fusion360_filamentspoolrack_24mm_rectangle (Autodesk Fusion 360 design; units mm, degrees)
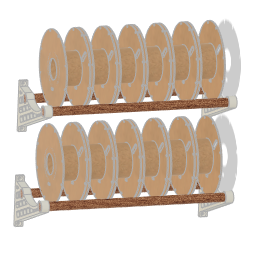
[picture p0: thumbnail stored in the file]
sketch "Skizze1" plane through (0, 0, 0) normal (0, 1, 0) x axis (1, 0, 0)
  circle C1 centre (0, 0) radius 27
  circle C2 centre (0, 0) radius 44
  circle C3 centre (0, 0) radius 41
  circle C4 centre (0, 0) radius 99.5
  point P1 (0, 0)
  point P2 (0, 0)
  coincident P1 P2
  concentric C1 C2
  concentric C2 C3
  concentric C3 C4
  dimension "d1" diameter C1 = 54
  dimension "d2" diameter C2 = 88
  dimension "d3" diameter C3 = 82
  dimension "d4" diameter C4 = 199
extrude "Extrusion1" new body sketch "Skizze1" against normal blind 3 bodies "cardboard spool 1"
extrude "Extrusion2" add sketch "Skizze1" profile of C2 C3 along normal blind 58
sketch "Skizze2" plane through (0, 58, 0) normal (0, 1, 0) x axis (-1, 0, 0)
  circle C1 centre (0, 0) radius 41
  circle C2 centre (0, 0) radius 44
  circle C3 centre (0, 0) radius 27
  circle C4 centre (0, 0) radius 99.5
  concentric C1 C3
  concentric C3 C4
  dimension "d9" diameter C3 = 54
  dimension "d10" diameter C4 = 199
extrude "Extrusion3" add sketch "Skizze2" along normal blind 3
sketch "Skizze3" plane through (0, -3, 0) normal (0, -1, 0) x axis (1, 0, 0)
  line L1 (-46.2426, 27.7574) -> (-64.2426, 45.7574)
  line L2 (-55.7574, 54.2426) -> (-37.7574, 36.2426)
  line L3 (-42, 32) -> (-60, 50)
  circle C1 centre (0, 0) radius 27
  circle C2 centre (0, 0) radius 99.5
  arc A1 centre (-42, 32) radius 6 clockwise from (-37.7574, 36.2426) to (-46.2426, 27.7574)
  arc A2 centre (-60, 50) radius 6 clockwise from (-64.2426, 45.7574) to (-55.7574, 54.2426)
  tangent L1 A1
  tangent A1 L2
  parallel L1 L2
  tangent L2 A2
  tangent L1 A2
  dimension "d13" diameter A1 = 12
extrude "Extrusion4" cut sketch "Skizze3" profile of L1 A1 L2 A2 against normal blind 3
sketch "Skizze4" plane through (0, -3, 0) normal (0, -1, 0) x axis (1, 0, 0)
  line L1 (-64.2426, 45.7574) -> (-46.2426, 27.7574)
  line L2 (-37.7574, 36.2426) -> (-55.7574, 54.2426)
  line L3 (4, -53) -> (-4, -53)
  line L4 (-4, -47) -> (4, -47)
  line L5 (4, -50) -> (-4, -50)
  arc A1 centre (-60, 50) radius 6 clockwise from (-64.2426, 45.7574) to (-55.7574, 54.2426)
  arc A2 centre (-42, 32) radius 6 clockwise from (-37.7574, 36.2426) to (-46.2426, 27.7574)
  circle C1 centre (0, 0) radius 27
  circle C2 centre (0, 0) radius 99.5
  circle C3 centre (-30, 90) radius 3
  circle C4 centre (30, 90) radius 3
  circle C5 centre (-90, -30) radius 3
  circle C6 centre (-90, 30) radius 3
  circle C7 centre (30, -90) radius 3
  circle C8 centre (-30, -90) radius 3
  circle C9 centre (90, -30) radius 3
  circle C10 centre (90, 30) radius 3
  arc A3 centre (4, -50) radius 3 clockwise from (4, -47) to (4, -53)
  arc A4 centre (-4, -50) radius 3 clockwise from (-4, -53) to (-4, -47)
  tangent L3 A3
  tangent A3 L4
  parallel L3 L4
  tangent L4 A4
  tangent L3 A4
  horizontal L5
  dimension "d16" diameter C3 = 6
  dimension "d17" diameter C4 = 6
  dimension "d18" diameter C5 = 6
  dimension "d19" diameter C6 = 6
  dimension "d20" diameter C7 = 6
  dimension "d21" diameter C8 = 6
  dimension "d22" diameter C9 = 6
  dimension "d23" diameter C10 = 6
  dimension "d24" diameter A3 = 6
extrude "Extrusion5" cut sketch "Skizze4" profile of C3 C4 C5 C6 C7 C8 C9 C10 L3 A3 L4 A4 against normal blind 100
sketch "Skizze5" plane through (0, -3, 0) normal (0, -1, 0) x axis (1, 0, 0)
  line L1 (-4, -53) -> (4, -53)
  line L2 (4, -47) -> (-4, -47)
  line L3 (-64.2426, 45.7574) -> (-46.2426, 27.7574)
  line L4 (-37.7574, 36.2426) -> (-55.7574, 54.2426)
  line L5 (60, -79.3741) -> (-60, -79.3741)
  line L6 (114, -179.9929) -> (114, 0.0071)
  line L7 (103.9489, -179.9929) -> (114, -179.9929)
  line L8 (103.9489, -51.9929) -> (103.9489, -179.9929)
  line L9 (114, -51.9929) -> (103.9489, -51.9929)
  line L10 (114, -179.9929) -> (114, -51.9929)
  line L11 (-71.8455, -102.3262) -> (103.9489, -166.9789)
  line L12 (103.9489, -158.9789) -> (103.9489, -166.9789)
  line L13 (-57.0574, -99.7649) -> (103.9489, -158.9789)
  line L14 (-46.0337, -97.145) -> (-48.1959, -103.024)
  line L15 (-43.5032, -104.7498) -> (-48.1959, -103.024)
  line L16 (-41.4565, -99.1847) -> (-43.5032, -104.7498)
  line L17 (-24.7324, -111.6533) -> (-43.5032, -104.7498)
  line L18 (-22.3416, -105.1528) -> (-24.7324, -111.6533)
  line L19 (-20.0397, -113.3791) -> (-24.7324, -111.6533)
  line L20 (-17.3586, -106.0892) -> (-20.0397, -113.3791)
  line L21 (-1.2689, -120.2825) -> (-20.0397, -113.3791)
  line L22 (3.4526, -107.4445) -> (-1.2689, -120.2825)
  line L23 (3.4238, -122.0084) -> (-1.2689, -120.2825)
  line L24 (8.8952, -107.1313) -> (3.4238, -122.0084)
  line L25 (22.1946, -128.9118) -> (3.4238, -122.0084)
  line L26 (31.8437, -102.6753) -> (22.1946, -128.9118)
  line L27 (26.8873, -130.6377) -> (22.1946, -128.9118)
  line L28 (37.9411, -100.5819) -> (26.8873, -130.6377)
  line L29 (45.6581, -137.5411) -> (26.8873, -130.6377)
  line L30 (59.1644, -100.8167) -> (45.6581, -137.5411)
  line L31 (50.3508, -139.2669) -> (45.6581, -137.5411)
  line L32 (63.8094, -102.6724) -> (50.3508, -139.2669)
  line L33 (69.1216, -146.1704) -> (50.3508, -139.2669)
  line L34 (73.8143, -147.8962) -> (69.1216, -146.1704)
  line L35 (103.9489, -65.9929) -> (103.9489, -51.9929)
  line L36 (69.5546, -73.2336) -> (103.9489, -65.9929)
  line L37 (103.9489, -73.9929) -> (103.9489, -65.9929)
  line L38 (79.1273, -79.2184) -> (103.9489, -73.9929)
  line L39 (94.9716, -75.8828) -> (69.1216, -146.1704)
  line L40 (100.7461, -74.6672) -> (73.8143, -147.8962)
  line L41 (92.5851, -154.7996) -> (73.8143, -147.8962)
  line L42 (103.9489, -123.9008) -> (92.5851, -154.7996)
  line L43 (98.0565, -139.9226) -> (8.8952, -107.1313)
  line L44 (100.8179, -132.4143) -> (98.0565, -139.9226)
  line L45 (25.0366, -104.5439) -> (100.8179, -132.4143)
  line L46 (45.9937, -97.1639) -> (103.9489, -118.4784)
  line L47 (106.7103, -110.9701) -> (103.9489, -118.4784)
  line L48 (76.276, -99.7771) -> (106.7103, -110.9701)
  line L49 (103.9489, -85.3915) -> (84.2383, -78.1424)
  line L50 (81.4769, -85.6507) -> (84.2383, -78.1424)
  line L51 (103.9489, -93.2715) -> (81.6855, -85.0836)
  circle C1 centre (-30, 90) radius 3
  circle C2 centre (30, -90) radius 3
  circle C3 centre (-30, -90) radius 3
  circle C4 centre (-90, 30) radius 3
  circle C5 centre (90, 30) radius 3
  circle C6 centre (90, -30) radius 3
  arc A1 centre (-4, -50) radius 3 clockwise from (-4, -53) to (-4, -47)
  arc A2 centre (4, -50) radius 3 clockwise from (4, -47) to (4, -53)
  circle C7 centre (-90, -30) radius 3
  circle C8 centre (30, 90) radius 3
  arc A3 centre (-60, 50) radius 6 clockwise from (-64.2426, 45.7574) to (-55.7574, 54.2426)
  arc A4 centre (-42, 32) radius 6 clockwise from (-37.7574, 36.2426) to (-46.2426, 27.7574)
  circle C9 centre (0, 0) radius 27
  circle C10 centre (0, 0) radius 99.5
  circle C11 centre (-66.6679, -88.2481) radius 11.1
  circle C12 centre (66.9737, -88.0099) radius 11.1
  circle C13 centre (-66.6679, -88.2481) radius 15
  circle C14 centre (66.9737, -88.0099) radius 15
  circle C15 centre (0, 0) radius 101
  circle C16 centre (0, 0) radius 107.5
  point P24 (-60, -79.3741)
  point P25 (60, -79.3741)
  point P1 (0, 0)
  point P29 (0, 0)
  point P36 (103.9489, -166.9789)
  point P37 (-71.8455, -102.3262)
  point P39 (-57.0574, -99.7649)
  point P40 (-48.1959, -103.024)
  point P41 (-46.0337, -97.145)
  point P43 (-41.4565, -99.1847)
  point P45 (-22.3416, -105.1528)
  point P47 (-17.3586, -106.0892)
  point P49 (3.4526, -107.4445)
  point P51 (8.8952, -107.1313)
  point P53 (31.8437, -102.6753)
  point P55 (37.9411, -100.5819)
  point P57 (59.1644, -100.8167)
  point P59 (63.8094, -102.6724)
  point P63 (69.5546, -73.2336)
  point P65 (79.1273, -79.2184)
  point P66 (94.9716, -75.8828)
  point P67 (100.7461, -74.6672)
  point P69 (103.9489, -123.9008)
  point P70 (98.0565, -139.9226)
  point P72 (25.0366, -104.5439)
  point P73 (103.9489, -118.4784)
  point P74 (45.9937, -97.1639)
  point P76 (76.276, -99.7771)
  point P77 (84.2383, -78.1424)
  point P78 (103.9489, -85.3915)
  point P80 (81.6855, -85.0836)
  point P81 (103.9489, -93.2715)
  point P31 (114, 0.0071)
  point P32 (114, -179.9929)
  point P35 (114, -51.9929)
  point P38 (103.9489, -158.9789)
  point P42 (-43.5032, -104.7498)
  point P44 (-24.7324, -111.6533)
  point P46 (-20.0397, -113.3791)
  point P48 (-1.2689, -120.2825)
  point P50 (3.4238, -122.0084)
  point P52 (22.1946, -128.9118)
  point P54 (26.8873, -130.6377)
  point P56 (45.6581, -137.5411)
  point P58 (50.3508, -139.2669)
  point P60 (69.1216, -146.1704)
  point P61 (73.8143, -147.8962)
  point P34 (103.9489, -51.9929)
  point P62 (103.9489, -65.9929)
  point P64 (103.9489, -73.9929)
  point P68 (92.5851, -154.7996)
  point P71 (100.8179, -132.4143)
  point P75 (106.7103, -110.9701)
  point P79 (81.4769, -85.6507)
  coincident C11 P24
  coincident C10 P24
  coincident C10 P25
  horizontal L5
  coincident P25 C12
  concentric C11 C13
  concentric C12 C14
  coincident P1 P29
  concentric C9 C16
  vertical L6
  horizontal L7
  vertical L8
  horizontal L9
  vertical L10
  coincident L8 P36
  coincident C13 P37
  tangent C13 L11
  parallel L8 L12
  coincident C13 P39
  parallel L11 L13
  coincident L13 P40
  coincident C16 P41
  perpendicular L13 L14
  perpendicular L14 L15
  coincident C16 P43
  perpendicular L15 L16
  perpendicular L16 L17
  coincident C16 P45
  perpendicular L13 L18
  perpendicular L18 L19
  coincident C16 P47
  perpendicular L13 L20
  perpendicular L20 L21
  coincident C16 P49
  perpendicular L13 L22
  perpendicular L22 L23
  coincident C16 P51
  perpendicular L23 L24
  perpendicular L24 L25
  coincident C16 P53
  perpendicular L13 L26
  perpendicular L26 L27
  coincident C16 P55
  perpendicular L13 L28
  perpendicular L28 L29
  coincident C14 P57
  perpendicular L29 L30
  perpendicular L30 L31
  coincident C14 P59
  perpendicular L31 L32
  perpendicular L32 L33
  perpendicular L28 L34
  perpendicular L9 L35
  coincident C15 P63
  coincident C14 P63
  parallel L8 L37
  coincident C14 P65
  parallel L36 L38
  coincident L38 P66
  perpendicular L33 L39
  coincident L38 P67
  perpendicular L34 L40
  perpendicular L40 L41
  coincident L8 P69
  perpendicular L13 L42
  coincident L42 P70
  perpendicular L42 L43
  perpendicular L43 L44
  coincident C16 P72
  perpendicular L26 L45
  coincident L8 P73
  coincident C16 P74
  perpendicular L30 L46
  perpendicular L46 L47
  coincident C14 P76
  perpendicular L39 L48
  coincident L38 P77
  coincident L8 P78
  perpendicular L40 L49
  perpendicular L49 L50
  coincident C14 P80
  coincident L50 P80
  coincident L8 P81
  perpendicular L40 L51
  dimension "d27" diameter C11 = 22.2
  dimension "d28" diameter C12 = 22.2
  dimension "d29" diameter C13 = 30
  dimension "d30" diameter C14 = 30
  dimension "d31" diameter C15 = 202
  dimension "d32" diameter C16 = 215
  dimension "d33" distance P31 P32 = 180
  dimension "d34" distance P32 P35 = 128
  dimension "d35" distance P36 P38 = 8
  dimension "d36" distance P40 P42 = 5
  dimension "d37" distance P42 P44 = 20
  dimension "d38" distance P44 P46 = 5
  dimension "d39" distance P46 P48 = 20
  dimension "d40" distance P48 P50 = 5
  dimension "d41" distance P50 P52 = 20
  dimension "d42" distance P52 P54 = 5
  dimension "d43" distance P54 P56 = 20
  dimension "d44" distance P56 P58 = 5
  dimension "d45" distance P58 P60 = 20
  dimension "d46" distance P60 P61 = 5
  dimension "d47" distance P34 P62 = 14
  dimension "d48" distance P62 P64 = 8
  dimension "d49" distance P61 P68 = 20
  dimension "d50" distance P70 P71 = 8
  dimension "d51" distance P73 P75 = 8
  dimension "d52" distance P77 P79 = 8
extrude "Extrusion6" new body sketch "Skizze5" profile of C10 C11 L5 C12 C13 C14 C15 C16 L6 L7 L8 L9 L10 L11 L12 L13 L14 L15 L16 L17 L18 L19 L20 L21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 along normal blind 20
sketch "Skizze6" plane through (103.9489, 0, 0) normal (-1, 0, 0) x axis (0, 0, 1)
  line L1 (-65.9929, -3) -> (-51.9929, -3)
  line L2 (-65.9929, -23) -> (-65.9929, -3)
  line L3 (-51.9929, -23) -> (-65.9929, -23)
  line L4 (-51.9929, -3) -> (-51.9929, -23)
  circle C1 centre (-59, -13) radius 2.5
  dimension "d55" diameter C1 = 5
sketch "Skizze7" plane through (103.9489, 0, 0) normal (-1, 0, 0) x axis (0, 0, 1)
  line L1 (-179.9929, -3) -> (-166.9789, -3)
  line L2 (-179.9929, -23) -> (-179.9929, -3)
  line L3 (-166.9789, -23) -> (-179.9929, -23)
  line L4 (-166.9789, -3) -> (-166.9789, -23)
  circle C1 centre (-173, -13) radius 2.5
  dimension "d56" diameter C1 = 5
extrude "Extrusion7" cut sketch "Skizze6" + "Skizze7" profile of S1:C1 S2:C1 blind -15
fillet "Abrundung1" radius 2
fillet "Abrundung2" radius 1
chamfer "Fase" distance 4
sketch "Skizze8" plane through (0, -3, 0) normal (0, 1, 0) x axis (-1, 0, 0)
  line L1 (23.1301, -107.2966) -> (24.042, -109.7762)
  line L2 (42.8128, -102.8728) -> (42.1706, -101.1266)
  line L3 (26.6094, -110.9629) -> (41.6261, -105.4402)
  line L4 (-81.5517, -112.3722) -> (-78.0447, -121.9079)
  line L5 (-65.3483, -104.2821) -> (-80.365, -109.8048)
  line L6 (-59.2739, -115.0045) -> (-62.7809, -105.4688)
  line L7 (-75.4773, -123.0947) -> (-60.4607, -117.5719)
  line L8 (46.6592, -98.8457) -> (47.5055, -101.1469)
  line L9 (50.0729, -102.3336) -> (54.1541, -100.8327)
  line L10 (-81.1628, -133.7095) -> (-96.1794, -139.2322)
  line L11 (-74.5047, -146.0191) -> (-78.5954, -134.8962)
  line L12 (-90.708, -154.1093) -> (-75.6914, -148.5865)
  line L13 (-97.3662, -141.7997) -> (-93.2755, -152.9225)
  line L14 (-103.9489, -119.8738) -> (-103.9489, -123.5447)
  line L15 (-88.8118, -112.9114) -> (-102.6393, -117.9967)
  line L16 (-82.7374, -123.6338) -> (-86.2444, -114.0981)
  line L17 (-98.9408, -131.7239) -> (-83.9242, -126.2012)
  line L18 (-103.826, -124.235) -> (-101.5082, -130.5372)
  line L19 (-98.3438, -81.1991) -> (-100.0718, -76.5005)
  line L20 (-101.2586, -84.402) -> (-99.5306, -83.7665)
  line L21 (-103.9489, -77.1908) -> (-103.9489, -82.525)
  line L22 (-57.6993, -125.0802) -> (-72.7159, -130.603)
  line L23 (-51.0412, -137.3899) -> (-55.1319, -126.267)
  line L24 (-67.2445, -145.48) -> (-52.2279, -139.9573)
  line L25 (-73.9027, -133.1704) -> (-69.812, -144.2933)
  line L26 (-34.2358, -116.451) -> (-49.2524, -121.9737)
  line L27 (-27.5777, -128.7606) -> (-31.6684, -117.6377)
  line L28 (-43.781, -136.8507) -> (-28.7644, -131.328)
  line L29 (-50.4392, -124.5411) -> (-46.3485, -135.664)
  line L30 (-96.9778, -90.7077) -> (-102.6393, -92.7898)
  line L31 (-90.3864, -102.8356) -> (-94.4103, -91.8944)
  line L32 (-101.2586, -108.9651) -> (-91.5732, -105.403)
  line L33 (-103.9489, -94.6669) -> (-103.9489, -107.088)
  line L34 (-93.7241, -79.2748) -> (-93.6511, -79.4732)
  line L35 (-91.0455, -76.7094) -> (-91.435, -76.6273)
  line L36 (-91.0837, -80.66) -> (-90.7671, -80.5435)
  line L37 (-84.664, -86.179) -> (-88.5309, -87.6011)
  line L38 (-83.1263, -102.2965) -> (-79.2565, -100.8733)
  line L39 (-89.7176, -90.1686) -> (-85.6937, -101.1098)
  line L40 (-2.4433, -110.1889) -> (0.5785, -118.4055)
  line L41 (19.3493, -111.502) -> (17.9243, -107.6274)
  line L42 (3.1459, -119.5922) -> (18.1626, -114.0695)
  line L43 (-31.1531, -104.5533) -> (-30.7726, -105.5879)
  line L44 (-29.4888, -106.1813) -> (-28.0577, -105.6549)
  line L45 (-58.0882, -103.743) -> (-54.5812, -113.2786)
  line L46 (-46.777, -97.452) -> (-56.9015, -101.1756)
  line L47 (-35.8104, -106.3752) -> (-37.6272, -101.4354)
  line L48 (-52.0138, -114.4654) -> (-36.9972, -108.9426)
  line L49 (-26.9757, -115.9118) -> (-22.885, -127.0347)
  line L50 (-10.7723, -107.8217) -> (-25.7889, -113.3444)
  line L51 (-4.1142, -120.1313) -> (-8.2049, -109.0084)
  line L52 (-20.3175, -128.2215) -> (-5.3009, -122.6987)
  line L53 (-103.9489, -51.9929) -> (-103.9489, -65.9929)
  line L54 (-114, -51.9929) -> (-103.9489, -51.9929)
  line L55 (-114, -179.9929) -> (-114, -51.9929)
  line L56 (-103.9489, -179.9929) -> (-114, -179.9929)
  line L57 (-103.9489, -166.9789) -> (-103.9489, -179.9929)
  line L58 (71.8455, -102.3262) -> (-103.9489, -166.9789)
  line L59 (-103.9489, -65.9929) -> (-69.5546, -73.2336)
  arc A1 centre (25.9191, -109.0858) radius 2 clockwise from (26.6094, -110.9629) to (24.042, -109.7762)
  arc A2 centre (25.0072, -106.6062) radius 2 clockwise from (23.1301, -107.2966) to (24.5504, -104.6591)
  arc A3 centre (0, 0) radius 107.5 clockwise from (39.5576, -99.9572) to (24.5504, -104.6591)
  arc A4 centre (40.2935, -101.8169) radius 2 clockwise from (39.5576, -99.9572) to (42.1706, -101.1266)
  arc A5 centre (40.9357, -103.5631) radius 2 clockwise from (42.8128, -102.8728) to (41.6261, -105.4402)
  arc A6 centre (-76.1676, -121.2176) radius 2 clockwise from (-75.4773, -123.0947) to (-78.0447, -121.9079)
  arc A7 centre (-79.6746, -111.6819) radius 2 clockwise from (-81.5517, -112.3722) to (-80.365, -109.8048)
  arc A8 centre (-64.658, -106.1592) radius 2 clockwise from (-65.3483, -104.2821) to (-62.7809, -105.4688)
  arc A9 centre (-61.151, -115.6948) radius 2 clockwise from (-59.2739, -115.0045) to (-60.4607, -117.5719)
  arc A10 centre (49.3826, -100.4566) radius 2 clockwise from (50.0729, -102.3336) to (47.5055, -101.1469)
  arc A11 centre (48.5363, -98.1554) radius 2 clockwise from (46.6592, -98.8457) to (47.6498, -96.3626)
  arc A12 centre (0, 0) radius 107.5 clockwise from (50.8463, -94.7149) to (47.6498, -96.3626)
  arc A13 centre (51.7923, -96.477) radius 2 clockwise from (50.8463, -94.7149) to (53.5423, -95.5089)
  arc A14 centre (66.6679, -88.2481) radius 15 clockwise from (55.0172, -97.6959) to (53.5423, -95.5089)
  arc A15 centre (53.4638, -98.9556) radius 2 clockwise from (55.0172, -97.6959) to (54.1541, -100.8327)
  arc A16 centre (-95.4891, -141.1093) radius 2 clockwise from (-97.3662, -141.7997) to (-96.1794, -139.2322)
  arc A17 centre (-80.4724, -135.5866) radius 2 clockwise from (-81.1628, -133.7095) to (-78.5954, -134.8962)
  arc A18 centre (-76.3817, -146.7095) radius 2 clockwise from (-74.5047, -146.0191) to (-75.6914, -148.5865)
  arc A19 centre (-91.3984, -152.2322) radius 2 clockwise from (-90.708, -154.1093) to (-93.2755, -152.9225)
  arc A20 centre (-101.9489, -123.5447) radius 2 clockwise from (-103.826, -124.235) to (-103.9489, -123.5447)
  arc A21 centre (-101.9489, -119.8738) radius 2 clockwise from (-103.9489, -119.8738) to (-102.6393, -117.9967)
  arc A22 centre (-88.1215, -114.7884) radius 2 clockwise from (-88.8118, -112.9114) to (-86.2444, -114.0981)
  arc A23 centre (-84.6145, -124.3241) radius 2 clockwise from (-82.7374, -123.6338) to (-83.9242, -126.2012)
  arc A24 centre (-99.6311, -129.8468) radius 2 clockwise from (-98.9408, -131.7239) to (-101.5082, -130.5372)
  arc A25 centre (-101.9489, -77.1908) radius 2 clockwise from (-103.9489, -77.1908) to (-100.0718, -76.5005)
  arc A26 centre (-100.2209, -81.8894) radius 2 clockwise from (-98.3438, -81.1991) to (-99.5306, -83.7665)
  arc A27 centre (-101.9489, -82.525) radius 2 clockwise from (-101.2586, -84.402) to (-103.9489, -82.525)
  circle C1 centre (66.6679, -88.2481) radius 11.1
  arc A28 centre (-72.0256, -132.48) radius 2 clockwise from (-73.9027, -133.1704) to (-72.7159, -130.603)
  arc A29 centre (-57.009, -126.9573) radius 2 clockwise from (-57.6993, -125.0802) to (-55.1319, -126.267)
  arc A30 centre (-52.9182, -138.0802) radius 2 clockwise from (-51.0412, -137.3899) to (-52.2279, -139.9573)
  arc A31 centre (-67.9349, -143.6029) radius 2 clockwise from (-67.2445, -145.48) to (-69.812, -144.2933)
  arc A32 centre (-48.5621, -123.8508) radius 2 clockwise from (-50.4392, -124.5411) to (-49.2524, -121.9737)
  arc A33 centre (-33.5455, -118.328) radius 2 clockwise from (-34.2358, -116.451) to (-31.6684, -117.6377)
  arc A34 centre (-29.4547, -129.4509) radius 2 clockwise from (-27.5777, -128.7606) to (-28.7644, -131.328)
  arc A35 centre (-44.4714, -134.9737) radius 2 clockwise from (-43.781, -136.8507) to (-46.3485, -135.664)
  arc A36 centre (-101.9489, -94.6669) radius 2 clockwise from (-103.9489, -94.6669) to (-102.6393, -92.7898)
  arc A37 centre (-96.2874, -92.5848) radius 2 clockwise from (-96.9778, -90.7077) to (-94.4103, -91.8944)
  arc A38 centre (-92.2635, -103.526) radius 2 clockwise from (-90.3864, -102.8356) to (-91.5732, -105.403)
  arc A39 centre (-101.9489, -107.088) radius 2 clockwise from (-101.2586, -108.9651) to (-103.9489, -107.088)
  arc A40 centre (-91.774, -78.7829) radius 2 clockwise from (-91.0837, -80.66) to (-93.6511, -79.4732)
  arc A41 centre (-91.847, -78.5845) radius 2 clockwise from (-93.7241, -79.2748) to (-91.435, -76.6273)
  arc A42 centre (-91.4575, -78.6665) radius 2 clockwise from (-91.0455, -76.7094) to (-90.7671, -80.5435)
  circle C2 centre (-66.9737, -88.0099) radius 11.1
  arc A43 centre (-87.8406, -89.4782) radius 2 clockwise from (-89.7176, -90.1686) to (-88.5309, -87.6011)
  arc A44 centre (-83.9737, -88.0561) radius 2 clockwise from (-84.664, -86.179) to (-81.9737, -88.0506)
  arc A45 centre (-66.9737, -88.0099) radius 15 clockwise from (-78.4206, -97.7037) to (-81.9737, -88.0506)
  arc A46 centre (-79.9468, -98.9962) radius 2 clockwise from (-78.4206, -97.7037) to (-79.2565, -100.8733)
  arc A47 centre (-83.8167, -100.4194) radius 2 clockwise from (-83.1263, -102.2965) to (-85.6937, -101.1098)
  arc A48 centre (2.4556, -117.7151) radius 2 clockwise from (3.1459, -119.5922) to (0.5785, -118.4055)
  arc A49 centre (-0.5662, -109.4985) radius 2 clockwise from (-2.4433, -110.1889) to (-0.5559, -107.4986)
  arc A50 centre (0, 0) radius 107.5 clockwise from (15.7542, -106.3393) to (-0.5559, -107.4986)
  arc A51 centre (16.0473, -108.3178) radius 2 clockwise from (15.7542, -106.3393) to (17.9243, -107.6274)
  arc A52 centre (17.4722, -112.1924) radius 2 clockwise from (19.3493, -111.502) to (18.1626, -114.0695)
  arc A53 centre (-29.834, -105.2427) radius 1 clockwise from (-29.4888, -106.1813) to (-30.7726, -105.5879)
  arc A54 centre (-30.2145, -104.2081) radius 1 clockwise from (-31.1531, -104.5533) to (-29.936, -103.2477)
  arc A55 centre (0, 0) radius 107.5 clockwise from (-28.1411, -103.7513) to (-29.936, -103.2477)
  arc A56 centre (-28.4029, -104.7164) radius 1 clockwise from (-28.1411, -103.7513) to (-28.0577, -105.6549)
  arc A57 centre (-52.7041, -112.5883) radius 2 clockwise from (-52.0138, -114.4654) to (-54.5812, -113.2786)
  arc A58 centre (-56.2111, -103.0526) radius 2 clockwise from (-58.0882, -103.743) to (-56.9015, -101.1756)
  arc A59 centre (-46.0866, -99.3291) radius 2 clockwise from (-46.777, -97.452) to (-45.2449, -97.5149)
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  dimension "d64" diameter = 24
  dimension "d65" diameter = 24
extrude "Extrusion8" cut sketch "Skizze8" against normal blind 20
sketch "Skizze9" plane through (0, -23, 0) normal (0, -1, 0) x axis (1, 0, 0)
  line L1 (103.9489, -82.525) -> (103.9489, -77.1908)
  line L2 (99.5306, -83.7665) -> (101.2586, -84.402)
  line L3 (100.0718, -76.5005) -> (98.3438, -81.1991)
  line L4 (46.3485, -135.664) -> (50.4392, -124.5411)
  line L5 (28.7644, -131.328) -> (43.781, -136.8507)
  line L6 (31.6684, -117.6377) -> (27.5777, -128.7606)
  line L7 (49.2524, -121.9737) -> (34.2358, -116.451)
  line L8 (69.812, -144.2933) -> (73.9027, -133.1704)
  line L9 (52.2279, -139.9573) -> (67.2445, -145.48)
  line L10 (55.1319, -126.267) -> (51.0412, -137.3899)
  line L11 (72.7159, -130.603) -> (57.6993, -125.0802)
  line L12 (93.2755, -152.9225) -> (97.3662, -141.7997)
  line L13 (75.6914, -148.5865) -> (90.708, -154.1093)
  line L14 (78.5954, -134.8962) -> (74.5047, -146.0191)
  line L15 (96.1794, -139.2322) -> (81.1628, -133.7095)
  line L16 (-54.1541, -100.8327) -> (-50.0729, -102.3336)
  line L17 (-47.5055, -101.1469) -> (-46.6592, -98.8457)
  line L18 (-41.6261, -105.4402) -> (-26.6094, -110.9629)
  line L19 (-42.1706, -101.1266) -> (-42.8128, -102.8728)
  line L20 (-24.042, -109.7762) -> (-23.1301, -107.2966)
  line L21 (28.0577, -105.6549) -> (29.4888, -106.1813)
  line L22 (30.7726, -105.5879) -> (31.1531, -104.5533)
  line L23 (-18.1626, -114.0695) -> (-3.1459, -119.5922)
  line L24 (-17.9243, -107.6274) -> (-19.3493, -111.502)
  line L25 (-0.5785, -118.4055) -> (2.4433, -110.1889)
  line L26 (36.9972, -108.9426) -> (52.0138, -114.4654)
  line L27 (37.6272, -101.4354) -> (35.8104, -106.3752)
  line L28 (56.9015, -101.1756) -> (46.777, -97.452)
  line L29 (54.5812, -113.2786) -> (58.0882, -103.743)
  line L30 (5.3009, -122.6987) -> (20.3175, -128.2215)
  line L31 (8.2049, -109.0084) -> (4.1142, -120.1313)
  line L32 (25.7889, -113.3444) -> (10.7723, -107.8217)
  line L33 (22.885, -127.0347) -> (26.9757, -115.9118)
  line L34 (103.9489, -107.088) -> (103.9489, -94.6669)
  line L35 (91.5732, -105.403) -> (101.2586, -108.9651)
  line L36 (94.4103, -91.8944) -> (90.3864, -102.8356)
  line L37 (102.6393, -92.7898) -> (96.9778, -90.7077)
  line L38 (101.5082, -130.5372) -> (103.826, -124.235)
  line L39 (83.9242, -126.2012) -> (98.9408, -131.7239)
  line L40 (86.2444, -114.0981) -> (82.7374, -123.6338)
  line L41 (102.6393, -117.9967) -> (88.8118, -112.9114)
  line L42 (103.9489, -123.5447) -> (103.9489, -119.8738)
  line L43 (85.6937, -101.1098) -> (89.7176, -90.1686)
  line L44 (79.2565, -100.8733) -> (83.1263, -102.2965)
  line L45 (88.5309, -87.6011) -> (84.664, -86.179)
  line L46 (90.7671, -80.5435) -> (91.0837, -80.66)
  line L47 (91.435, -76.6273) -> (91.0455, -76.7094)
  line L48 (93.6511, -79.4732) -> (93.7241, -79.2748)
  line L49 (60.4607, -117.5719) -> (75.4773, -123.0947)
  line L50 (62.7809, -105.4688) -> (59.2739, -115.0045)
  line L51 (80.365, -109.8048) -> (65.3483, -104.2821)
  line L52 (78.0447, -121.9079) -> (81.5517, -112.3722)
  line L53 (103.9489, -65.9929) -> (103.9489, -51.9929)
  line L54 (69.5546, -73.2336) -> (103.9489, -65.9929)
  line L55 (103.9489, -166.9789) -> (-71.8455, -102.3262)
  line L56 (103.9489, -179.9929) -> (103.9489, -166.9789)
  line L57 (114, -179.9929) -> (103.9489, -179.9929)
  line L58 (114, -51.9929) -> (114, -179.9929)
  line L59 (103.9489, -51.9929) -> (114, -51.9929)
  circle C1 centre (66.9737, -88.0099) radius 12
  circle C2 centre (-66.6679, -88.2481) radius 12
  arc A1 centre (101.9489, -82.525) radius 2 clockwise from (103.9489, -82.525) to (101.2586, -84.402)
  arc A2 centre (100.2209, -81.8894) radius 2 clockwise from (99.5306, -83.7665) to (98.3438, -81.1991)
  arc A3 centre (101.9489, -77.1908) radius 2 clockwise from (100.0718, -76.5005) to (103.9489, -77.1908)
  arc A4 centre (44.4714, -134.9737) radius 2 clockwise from (46.3485, -135.664) to (43.781, -136.8507)
  arc A5 centre (29.4547, -129.4509) radius 2 clockwise from (28.7644, -131.328) to (27.5777, -128.7606)
  arc A6 centre (33.5455, -118.328) radius 2 clockwise from (31.6684, -117.6377) to (34.2358, -116.451)
  arc A7 centre (48.5621, -123.8508) radius 2 clockwise from (49.2524, -121.9737) to (50.4392, -124.5411)
  arc A8 centre (67.9349, -143.6029) radius 2 clockwise from (69.812, -144.2933) to (67.2445, -145.48)
  arc A9 centre (52.9182, -138.0802) radius 2 clockwise from (52.2279, -139.9573) to (51.0412, -137.3899)
  arc A10 centre (57.009, -126.9573) radius 2 clockwise from (55.1319, -126.267) to (57.6993, -125.0802)
  arc A11 centre (72.0256, -132.48) radius 2 clockwise from (72.7159, -130.603) to (73.9027, -133.1704)
  arc A12 centre (91.3984, -152.2322) radius 2 clockwise from (93.2755, -152.9225) to (90.708, -154.1093)
  arc A13 centre (76.3817, -146.7095) radius 2 clockwise from (75.6914, -148.5865) to (74.5047, -146.0191)
  arc A14 centre (80.4724, -135.5866) radius 2 clockwise from (78.5954, -134.8962) to (81.1628, -133.7095)
  arc A15 centre (95.4891, -141.1093) radius 2 clockwise from (96.1794, -139.2322) to (97.3662, -141.7997)
  arc A16 centre (-53.4638, -98.9556) radius 2 clockwise from (-54.1541, -100.8327) to (-55.0172, -97.6959)
  arc A17 centre (-66.6679, -88.2481) radius 15 clockwise from (-53.5423, -95.5089) to (-55.0172, -97.6959)
  arc A18 centre (-51.7923, -96.477) radius 2 clockwise from (-53.5423, -95.5089) to (-50.8463, -94.7149)
  arc A19 centre (0, 0) radius 107.5 clockwise from (-47.6498, -96.3626) to (-50.8463, -94.7149)
  arc A20 centre (-48.5363, -98.1554) radius 2 clockwise from (-47.6498, -96.3626) to (-46.6592, -98.8457)
  arc A21 centre (-49.3826, -100.4566) radius 2 clockwise from (-47.5055, -101.1469) to (-50.0729, -102.3336)
  arc A22 centre (-40.9357, -103.5631) radius 2 clockwise from (-41.6261, -105.4402) to (-42.8128, -102.8728)
  arc A23 centre (-40.2935, -101.8169) radius 2 clockwise from (-42.1706, -101.1266) to (-39.5576, -99.9572)
  arc A24 centre (0, 0) radius 107.5 clockwise from (-24.5504, -104.6591) to (-39.5576, -99.9572)
  arc A25 centre (-25.0072, -106.6062) radius 2 clockwise from (-24.5504, -104.6591) to (-23.1301, -107.2966)
  arc A26 centre (-25.9191, -109.0858) radius 2 clockwise from (-24.042, -109.7762) to (-26.6094, -110.9629)
  arc A27 centre (28.4029, -104.7164) radius 1 clockwise from (28.0577, -105.6549) to (28.1411, -103.7513)
  arc A28 centre (0, 0) radius 107.5 clockwise from (29.936, -103.2477) to (28.1411, -103.7513)
  arc A29 centre (30.2145, -104.2081) radius 1 clockwise from (29.936, -103.2477) to (31.1531, -104.5533)
  arc A30 centre (29.834, -105.2427) radius 1 clockwise from (30.7726, -105.5879) to (29.4888, -106.1813)
  arc A31 centre (-17.4722, -112.1924) radius 2 clockwise from (-18.1626, -114.0695) to (-19.3493, -111.502)
  arc A32 centre (-16.0473, -108.3178) radius 2 clockwise from (-17.9243, -107.6274) to (-15.7542, -106.3393)
  arc A33 centre (0, 0) radius 107.5 clockwise from (0.5559, -107.4986) to (-15.7542, -106.3393)
  arc A34 centre (0.5662, -109.4985) radius 2 clockwise from (0.5559, -107.4986) to (2.4433, -110.1889)
  arc A35 centre (-2.4556, -117.7151) radius 2 clockwise from (-0.5785, -118.4055) to (-3.1459, -119.5922)
  arc A36 centre (37.6875, -107.0656) radius 2 clockwise from (36.9972, -108.9426) to (35.8104, -106.3752)
  arc A37 centre (39.5043, -102.1257) radius 2 clockwise from (37.6272, -101.4354) to (38.7827, -100.2604)
  arc A38 centre (0, 0) radius 107.5 clockwise from (45.2449, -97.5149) to (38.7827, -100.2604)
  arc A39 centre (46.0866, -99.3291) radius 2 clockwise from (45.2449, -97.5149) to (46.777, -97.452)
  arc A40 centre (56.2111, -103.0526) radius 2 clockwise from (56.9015, -101.1756) to (58.0882, -103.743)
  arc A41 centre (52.7041, -112.5883) radius 2 clockwise from (54.5812, -113.2786) to (52.0138, -114.4654)
  arc A42 centre (5.9913, -120.8216) radius 2 clockwise from (5.3009, -122.6987) to (4.1142, -120.1313)
  arc A43 centre (10.082, -109.6988) radius 2 clockwise from (8.2049, -109.0084) to (10.7723, -107.8217)
  arc A44 centre (25.0986, -115.2215) radius 2 clockwise from (25.7889, -113.3444) to (26.9757, -115.9118)
  arc A45 centre (21.0079, -126.3444) radius 2 clockwise from (22.885, -127.0347) to (20.3175, -128.2215)
  arc A46 centre (101.9489, -107.088) radius 2 clockwise from (103.9489, -107.088) to (101.2586, -108.9651)
  arc A47 centre (92.2635, -103.526) radius 2 clockwise from (91.5732, -105.403) to (90.3864, -102.8356)
  arc A48 centre (96.2874, -92.5848) radius 2 clockwise from (94.4103, -91.8944) to (96.9778, -90.7077)
  arc A49 centre (101.9489, -94.6669) radius 2 clockwise from (102.6393, -92.7898) to (103.9489, -94.6669)
  arc A50 centre (99.6311, -129.8468) radius 2 clockwise from (101.5082, -130.5372) to (98.9408, -131.7239)
  arc A51 centre (84.6145, -124.3241) radius 2 clockwise from (83.9242, -126.2012) to (82.7374, -123.6338)
  arc A52 centre (88.1215, -114.7884) radius 2 clockwise from (86.2444, -114.0981) to (88.8118, -112.9114)
  arc A53 centre (101.9489, -119.8738) radius 2 clockwise from (102.6393, -117.9967) to (103.9489, -119.8738)
  arc A54 centre (101.9489, -123.5447) radius 2 clockwise from (103.9489, -123.5447) to (103.826, -124.235)
  arc A55 centre (83.8167, -100.4194) radius 2 clockwise from (85.6937, -101.1098) to (83.1263, -102.2965)
  arc A56 centre (79.9468, -98.9962) radius 2 clockwise from (79.2565, -100.8733) to (78.4206, -97.7037)
  arc A57 centre (66.9737, -88.0099) radius 15 clockwise from (81.9737, -88.0506) to (78.4206, -97.7037)
  arc A58 centre (83.9737, -88.0561) radius 2 clockwise from (81.9737, -88.0506) to (84.664, -86.179)
  arc A59 centre (87.8406, -89.4782) radius 2 clockwise from (88.5309, -87.6011) to (89.7176, -90.1686)
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  dimension "d68" diameter = 23.8
  dimension "d69" diameter = 23.8
extrude "Extrusion9" new body sketch "Skizze9" against normal blind 500 bodies "dowel 1", "dowel 2"
copy_paste_bodies "Körper kopieren/einfügen1"
move "Verschieben1"
move "Verschieben2"
copy_paste_bodies "Körper kopieren/einfügen2"
move "Verschieben3"
copy_paste_bodies "Körper kopieren/einfügen3"
move "Verschieben4"
copy_paste_bodies "Körper kopieren/einfügen4"
move "Verschieben5"
copy_paste_bodies "Körper kopieren/einfügen5"
move "Verschieben6"
copy_paste_bodies "Körper kopieren/einfügen6"
move "Verschieben7"
move "Verschieben8"
sketch "Skizze10" plane through (114, 0, 0) normal (1, 0, 0) x axis (0, 0, -1)
  line L1 (51.9929, -3) -> (179.9929, -3)
  line L2 (51.9929, -23) -> (51.9929, -3)
  line L3 (179.9929, -23) -> (51.9929, -23)
  line L4 (179.9929, -3) -> (179.9929, -23)
  line L5 (2076.3806, 1097.0415) -> (-942.1986, 1097.0415)
  line L6 (2076.3806, -894.5127) -> (2076.3806, 1097.0415)
  line L7 (-942.1986, -894.5127) -> (2076.3806, -894.5127)
  line L8 (-942.1986, 1097.0415) -> (-942.1986, -894.5127)
  circle C1 centre (59, -13) radius 2.5
  circle C2 centre (173, -13) radius 2.5
  horizontal L5
  vertical L6
  horizontal L7
  vertical L8
extrude "Extrusion10" new body sketch "Skizze10" along normal blind 5 bodies "Wall (1)"
copy_paste_bodies "Körper kopieren/einfügen7"
move "Verschieben9"
sketch "Skizze11" plane through (114, 0, 0) normal (-1, 0, 0) x axis (0, 0, 1)
  line L1 (942.1986, -894.5127) -> (-2076.3806, -894.5127)
  line L2 (942.1986, 1097.0415) -> (942.1986, -894.5127)
  line L3 (-2076.3806, 1097.0415) -> (942.1986, 1097.0415)
  line L4 (-2076.3806, -894.5127) -> (-2076.3806, 1097.0415)
  line L5 (-420, -30) -> (100, -30)
  line L6 (-420, -34) -> (-420, -30)
  line L7 (100, -34) -> (-420, -34)
  line L8 (100, -30) -> (100, -34)
  circle C1 centre (-173, -13) radius 2.5
  circle C2 centre (-59, -13) radius 2.5
  horizontal L5
  vertical L6
  horizontal L7
  vertical L8
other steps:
base_feature "Basiselement1" bodies "wall mount", "wall mount 2"
base_feature "Basiselement2" bodies "cardboard spool", "cardboard spool 2"
base_feature "Basiselement3" bodies "cardboard spool 2", "cardboard spool 3"
base_feature "Basiselement4" bodies "cardboard spool 3", "cardboard spool 4"
base_feature "Basiselement5" bodies "cardboard spool 4", "cardboard spool 5"
base_feature "Basiselement6" bodies "cardboard spool 5", "cardboard spool 6"
base_feature "Basiselement7" bodies "cardboard spool 1", "dowel 1", "dowel 2", "cardboard spool 5 (1)", "wall mount (1)", "wall mount 2", "cardboard spool 6", "cardboard spool 2 (1)"
named bodies: "cardboard spool 1", "wall mount", "dowel 1", "dowel 2", "wall mount 2", "cardboard spool", "cardboard spool 2", "cardboard spool 3", "cardboard spool 4", "cardboard spool 5", "cardboard spool 6", "Wall (1)", "cardboard spool 5 (1)", "wall mount (1)", "cardboard spool 2 (1)", "cardboard spool 3 (1)", "cardboard spool 4 (1)", "cardboard spool 1 (1)", "dowel 1 (1)", "dowel 2 (1)", "wall mount 2 (1)", "cardboard spool 6 (1)"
